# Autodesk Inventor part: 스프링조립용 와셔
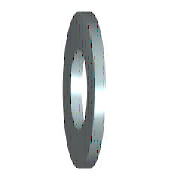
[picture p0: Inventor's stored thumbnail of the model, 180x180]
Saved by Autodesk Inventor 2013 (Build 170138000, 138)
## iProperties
IsCustomPart: 1
Created: 2012-02
Part Number: 스프링조립용 와셔
Material: 강철, 연강
Description: 평면 와셔
Document SubType Name: Modeling
Standard: KS B 1326
Designer: mduedu
Standards Organization: KS
Language: ko-KR
Size Designation: 12x24
Categories: <MemberInstance><Categories><Category DisplayName="조임쇠" InternalName="e4da775c-781d-43d5-af7c-5136215cf5a6" Mnemonic="FSTN"><Category DisplayName="와셔" InternalN
Density: 7.86 g/cm^3
Mass: 5.3954 g
Surface Area: 8.71478 cm^2
Volume: 0.686438 cm^3
Author: mduedu
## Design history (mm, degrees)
sketch "스케치"
  geometry: C1 r 12 at (0, 0); C2 r 7 at (0, 0); 1 further point
  constraints: 2 centre point, 2 coincident
  dimensions: "d0" = 14 diameter of C2 (= SD1); "d1" = 24 diameter of C1 (= SD2)
extrude "본체" new body sketch "스케치" distance "d2" = 2.3 (= SD); taper "d3" = 0 deg
workaxis "Work Axis1"
workplane "Work Plane1"
body "Solid1"
other parameters: "SD1" = 14 [user parameter; used in 1 equation term], "SD2" = 24 [user parameter; used in 1 equation term], "SD" = 2.3 [user parameter; used in 1 equation term], "d4" = 0, "d5" = 0, "d6" = 0, "d7" = 0, "NND" = 12 [user parameter]
